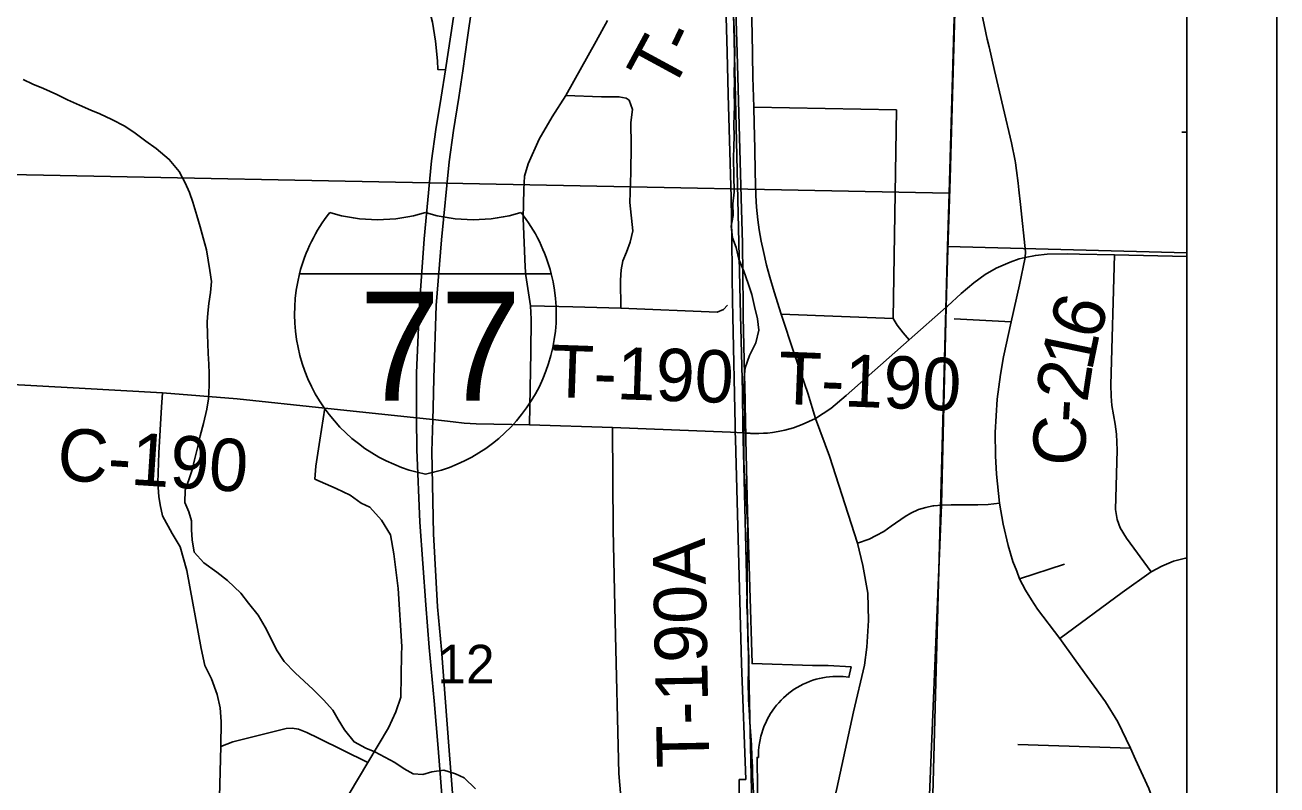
# Model space of a CAD drawing. Extents: x 0 to 34, y 0 to 22.
# Drawn here: x 8.376 to 9.735, y 19.213 to 20.038 of the extents above; entities that cross this region are included whole.
import ezdxf

# ---------------------------------------------------------------- set-up
doc = ezdxf.new("R2010")
doc.units = 0
for name, color, linetype in [('GM_X_City_Street', 7, 'Continuous'), ('GM_X_Corporation', 7, 'Continuous'), ('GM_X_County_Road', 7, 'Continuous'), ('GM_X_County_Road_Text', 7, 'Continuous'), ('GM_X_Interchange_Ramps', 7, 'Continuous'), ('GM_X_Interstate_Location', 7, 'Continuous'), ('GM_X_Interstate_Route', 7, 'Continuous'), ('GM_X_Interstate_Shield', 7, 'Continuous'), ('GM_X_Minor_River', 7, 'Continuous'), ('GM_X_Rail_Line', 7, 'Continuous'), ('GM_X_Section_Text', 7, 'Continuous'), ('GM_X_Township_Road', 7, 'Continuous'), ('GM_X_Township_Road_Text', 7, 'Continuous'), ('SH_Data', 7, 'Continuous')]:
    doc.layers.add(name, color=color, linetype=linetype)

msp = doc.modelspace()

# ---------------------------------------------------------------- linework, layer by layer
at = {"layer": 'GM_X_City_Street'}
for p, q in [((9.6316, 19.9223), (9.637, 19.9223)), ((9.4555, 19.4373), (9.5042, 19.453)), ((9.4535, 19.2572), (9.5759, 19.2532))]:
    msp.add_line(p, q, dxfattribs=at)
msp.add_lwpolyline([(9.5985, 19.4448), (9.5714, 19.4812), (9.5648, 19.4925), (9.5613, 19.5017), (9.5597, 19.5123), (9.56, 19.5251), (9.5614, 19.577), (9.5608, 19.5942), (9.5592, 19.6051), (9.5556, 19.6255), (9.5548, 19.6355), (9.5547, 19.6478), (9.5586, 19.7888)], dxfattribs=at)
at = {"layer": 'GM_X_Corporation'}
for points in [[(7.1023, 20.9204), (2.837, 20.9204), (2.837, 14.1204), (9.637, 14.1204), (9.637, 20.9204), (9.4036, 20.9204), (9.4022, 20.8667), (9.2273, 20.8723), (9.1354, 20.8749), (9.124, 20.8753), (8.9858, 20.878), (8.9676, 20.8785), (8.8663, 20.881), (8.6259, 20.8892), (8.5535, 20.8914), (8.5421, 20.8915), (8.4667, 20.8934), (8.0602, 20.9055), (7.9522, 20.9084), (7.1104, 20.9188)], [(9.637, 19.791), (9.637, 20.8648), (9.4079, 20.8705), (9.3789, 19.8558), (9.3773, 19.7981)], [(8.3589, 19.8763), (9.3789, 19.8558), (9.3773, 19.7981), (9.3514, 18.838), (8.3333, 18.8624)], [(9.637, 18.7908), (9.637, 19.791), (9.3773, 19.7981), (9.3514, 18.838), (9.3511, 18.8009)]]:
    msp.add_lwpolyline(points, close=True, dxfattribs=at)
for points in [[(9.637, 14.7553), (9.637, 20.8621)], [(9.3877, 20.1427), (9.3802, 19.8717), (9.377, 19.7721), (9.3757, 19.7325), (9.3706, 19.5177), (9.3568, 19.1851), (9.3573, 19.1731), (9.3575, 19.1703), (9.3577, 19.163), (9.3575, 19.1426), (9.3568, 19.1161), (9.3505, 18.9331), (9.349, 18.88), (9.3486, 18.8618), (9.3482, 18.8485), (9.3472, 18.8129), (9.347, 18.8053), (9.3432, 18.6624), (9.3419, 18.6564), (9.3421, 18.534), (9.3421, 18.502), (9.3401, 18.421), (9.3264, 18.0621)], [(9.3264, 18.0621), (9.3401, 18.421), (9.3421, 18.502), (9.3421, 18.534), (9.3419, 18.6564), (9.3432, 18.6624), (9.347, 18.8053), (9.3472, 18.8129), (9.3482, 18.8485), (9.3486, 18.8618), (9.349, 18.88), (9.3505, 18.9331), (9.3568, 19.1161), (9.3575, 19.1426), (9.3577, 19.163), (9.3575, 19.1703), (9.3573, 19.1731), (9.3568, 19.1851), (9.3706, 19.5177), (9.3757, 19.7325), (9.377, 19.7721), (9.3802, 19.8717), (9.3877, 20.1427)], [(9.1348, 20.1234), (9.138, 20.0088), (9.1392, 19.9629), (9.1422, 19.8512), (9.1429, 19.8057), (9.1439, 19.7345), (9.1439, 19.7335), (9.144, 19.7278), (9.1441, 19.7221), (9.1466, 19.604), (9.1468, 19.5972), (9.147, 19.5887), (9.1536, 19.3454), (9.1582, 19.2195), (9.1547, 19.2194), (9.1511, 19.2193), (9.1514, 19.1601)], [(9.1722, 19.0732), (9.1704, 19.2433), (9.1719, 19.2434), (9.1719, 19.2471), (9.1721, 19.2509), (9.1724, 19.2546), (9.173, 19.2588), (9.1737, 19.2625), (9.1746, 19.2662), (9.1756, 19.2698), (9.1767, 19.2734), (9.1783, 19.2775), (9.1798, 19.2809), (9.1814, 19.2843), (9.1832, 19.2876), (9.1851, 19.2909), (9.1893, 19.297), (9.1916, 19.2999), (9.194, 19.3027), (9.1965, 19.3055), (9.1992, 19.3081), (9.2019, 19.3106), (9.2048, 19.3129), (9.2078, 19.3152), (9.2109, 19.3173), (9.214, 19.3193), (9.2173, 19.3211), (9.2206, 19.3228), (9.224, 19.3243), (9.2274, 19.3257), (9.2309, 19.327), (9.2345, 19.3281), (9.2381, 19.329), (9.2417, 19.3298), (9.2454, 19.3304), (9.2491, 19.3309), (9.2528, 19.3311), (9.2565, 19.3313), (9.2603, 19.3312), (9.264, 19.3311), (9.2702, 19.3304), (9.2725, 19.3416), (9.2477, 19.343), (9.2307, 19.343), (9.165, 19.3451), (9.1602, 19.5104), (9.1584, 19.5883), (9.1582, 19.5968), (9.158, 19.6036), (9.1574, 19.6314), (9.1568, 19.6592), (9.1554, 19.7218), (9.1553, 19.7275), (9.1553, 19.7332), (9.1546, 19.8014), (9.1531, 19.8508), (9.1487, 20.0085), (9.1468, 20.0776)]]:
    msp.add_lwpolyline(points, dxfattribs=at)
at = {"layer": 'GM_X_County_Road'}
for points in [[(9.4223, 20.0149), (9.4203, 20.0231), (9.409, 20.0769), (9.4068, 20.0838), (9.4033, 20.0959), (9.3994, 20.1083), (9.3948, 20.1222)], [(9.1967, 19.7245), (9.1891, 19.7487), (9.1844, 19.7646), (9.1808, 19.7777), (9.1773, 19.7925), (9.175, 19.8039), (9.1728, 19.816), (9.1711, 19.8269), (9.1698, 19.8406), (9.1691, 19.8535), (9.1685, 19.8788), (9.1679, 19.9044), (9.1672, 19.9317), (9.1669, 19.9494), (9.166, 19.9817), (9.1651, 20.03), (9.1638, 20.0783)], [(9.4507, 19.8909), (9.4468, 19.9107), (9.4377, 19.949), (9.4284, 19.9892), (9.4223, 20.0149)], [(9.4547, 19.8596), (9.4538, 19.8666), (9.4521, 19.8806), (9.4511, 19.8889), (9.4507, 19.8909)], [(9.4617, 19.7862), (9.4618, 19.7921), (9.4566, 19.8435), (9.4547, 19.8596)], [(9.3772, 19.7332), (9.3922, 19.7469), (9.4057, 19.7585), (9.4181, 19.7676), (9.43, 19.7745), (9.4451, 19.7811), (9.4552, 19.7846), (9.4617, 19.7862)], [(9.4524, 19.4454), (9.4483, 19.4561), (9.4431, 19.4732), (9.4377, 19.4966), (9.4337, 19.5194), (9.4305, 19.5509), (9.4293, 19.5707), (9.4289, 19.5962), (9.4312, 19.6323), (9.4349, 19.659), (9.4381, 19.6781), (9.4465, 19.7161), (9.4554, 19.7563), (9.4617, 19.7862)], [(9.4617, 19.7862), (9.4727, 19.7884), (9.4853, 19.7897), (9.5079, 19.7901), (9.5206, 19.7898)], [(9.5206, 19.7898), (9.5586, 19.7888), (9.637, 19.7873)], [(9.1625, 19.5952), (9.1635, 19.5951), (9.1684, 19.595), (9.1725, 19.595), (9.1773, 19.5952), (9.1817, 19.5955), (9.1872, 19.5962), (9.1932, 19.5971), (9.2006, 19.5986), (9.2099, 19.6012), (9.2193, 19.6046), (9.234, 19.6114), (9.2506, 19.6222), (9.2672, 19.6362), (9.3357, 19.6968), (9.3759, 19.732), (9.3772, 19.7332)], [(9.243, 19.1481), (9.257, 19.2097), (9.2753, 19.2929), (9.2871, 19.3435), (9.2896, 19.3629), (9.2914, 19.3921), (9.2908, 19.4217), (9.2852, 19.4516), (9.2795, 19.4758), (9.2491, 19.5703), (9.234, 19.6114), (9.2257, 19.6387), (9.2108, 19.6817), (9.1967, 19.7245)], [(8.3488, 19.6489), (8.4344, 19.6443), (8.5247, 19.6393), (8.606, 19.6325), (8.701, 19.6225)], [(8.701, 19.6225), (8.8006, 19.612), (8.8183, 19.61), (8.8403, 19.6078), (8.8524, 19.6062), (8.8656, 19.6054), (8.9233, 19.6043), (9.0134, 19.6015), (9.1415, 19.5963)], [(9.1415, 19.5963), (9.1554, 19.5957), (9.1595, 19.5954), (9.1625, 19.5952)], [(9.2795, 19.4758), (9.2921, 19.4803), (9.2996, 19.4841), (9.308, 19.4887), (9.3161, 19.4942), (9.3314, 19.5049), (9.3375, 19.5086), (9.3456, 19.5124), (9.3536, 19.5147), (9.3614, 19.5163)], [(9.3614, 19.5163), (9.3624, 19.5165), (9.3708, 19.5172), (9.3812, 19.5174), (9.4102, 19.5175), (9.4214, 19.518), (9.4337, 19.5194)], [(9.4993, 19.3725), (9.5668, 19.4222), (9.5985, 19.4448), (9.6098, 19.4511), (9.6227, 19.4564), (9.6356, 19.4596), (9.637, 19.4598)], [(9.608, 19.176), (9.5958, 19.2096), (9.5815, 19.241), (9.5759, 19.2532), (9.5621, 19.2818), (9.5489, 19.3036), (9.5165, 19.3481), (9.4993, 19.3725), (9.4749, 19.4043), (9.4684, 19.4143), (9.462, 19.4248), (9.4555, 19.4373), (9.4524, 19.4454)]]:
    msp.add_lwpolyline(points, dxfattribs=at)
at = {"layer": 'GM_X_Interchange_Ramps'}
msp.add_lwpolyline([(8.6899, 20.3386), (8.6874, 20.3341), (8.6787, 20.3193), (8.6745, 20.3085), (8.6725, 20.3013), (8.6712, 20.2917), (8.6704, 20.283), (8.6712, 20.273), (8.6726, 20.2598), (8.6767, 20.2451), (8.6831, 20.2301), (8.7001, 20.2081), (8.7688, 20.1341), (8.7796, 20.1219), (8.7885, 20.1099), (8.7962, 20.0973), (8.805, 20.0811), (8.8125, 20.0622), (8.818, 20.0414), (8.8214, 20.0209), (8.8233, 19.9995), (8.8239, 19.9901), (8.832, 19.9897)], dxfattribs=at)
at = {"layer": 'GM_X_Interstate_Route'}
for points in [[(8.8273, 19.9603), (8.832, 19.9897), (8.8381, 20.0277), (8.8472, 20.0907), (8.8602, 20.1746), (8.8736, 20.2591), (8.8763, 20.2792), (8.8862, 20.3413), (8.8962, 20.4047), (8.9061, 20.4741), (8.9155, 20.533), (8.9181, 20.5506), (8.926, 20.5995), (8.9382, 20.6828), (8.9516, 20.774), (8.9678, 20.878)], [(8.8465, 19.9599), (8.8511, 19.9887), (8.8561, 20.0249), (8.8651, 20.0879), (8.8781, 20.1718), (8.8916, 20.2563), (8.8946, 20.2767), (8.9044, 20.3409), (8.9144, 20.4042), (8.9243, 20.4736), (8.9337, 20.5325), (8.937, 20.5487), (8.9564, 20.6824), (8.9699, 20.7735), (8.986, 20.8775)], [(8.8006, 19.6249), (8.8006, 19.6607), (8.8039, 19.7349), (8.8088, 19.8063), (8.817, 19.891), (8.8216, 19.925), (8.8273, 19.9603)], [(8.8186, 19.623), (8.8195, 19.6549), (8.822, 19.7339), (8.8279, 19.8053), (8.8361, 19.89), (8.8408, 19.9241), (8.8465, 19.9599)], [(8.8989, 18.3509), (8.895, 18.3799), (8.8917, 18.412), (8.8886, 18.4533), (8.8825, 18.5322), (8.8739, 18.6411), (8.8688, 18.703), (8.859, 18.8212), (8.8549, 18.8749), (8.8414, 19.0423), (8.8359, 19.1114), (8.8301, 19.1795), (8.8286, 19.198), (8.824, 19.2534), (8.8197, 19.3047), (8.8144, 19.3626), (8.8108, 19.4089), (8.8041, 19.4986), (8.8011, 19.5776), (8.8006, 19.612), (8.8006, 19.6249)], [(8.8406, 19.1954), (8.8361, 19.2508), (8.8278, 19.3603), (8.8236, 19.4067), (8.819, 19.486), (8.8172, 19.5753), (8.8183, 19.61), (8.8186, 19.623)]]:
    msp.add_lwpolyline(points, dxfattribs=at)
at = {"layer": 'GM_X_Interstate_Shield'}
for p, q in [((8.6736, 19.7683), (8.9469, 19.7683)), ((8.9469, 19.7683), (8.6736, 19.7683)), ((8.9469, 19.7683), (8.6736, 19.7683))]:
    msp.add_line(p, q, dxfattribs=at)
for centre, start, end in [((8.8458, 19.7248), 141.669, 165.8066), ((8.7584, 20.0047), 253.0091, 286.9909), ((8.8622, 20.0047), 253.0091, 286.9909), ((8.7748, 19.7248), 14.1934, 38.331), ((8.8458, 19.7248), 165.8066, 258.463), ((8.7748, 19.7248), 281.537, 14.1934)]:
    msp.add_arc(centre, 0.1776, start, end, dxfattribs=at)
at = {"layer": 'GM_X_Minor_River'}
for points in [[(9.145, 20.046), (9.1455, 20.035), (9.1461, 20.0205), (9.1462, 20.0099), (9.1459, 19.9985), (9.1457, 19.9867), (9.1458, 19.9761), (9.1456, 19.9659), (9.1458, 19.9507), (9.1455, 19.9404), (9.1453, 19.9305), (9.1454, 19.9176), (9.1452, 19.9066), (9.1449, 19.8937), (9.1454, 19.8569), (9.144, 19.8443), (9.1446, 19.8318), (9.1424, 19.82), (9.1437, 19.8075), (9.1476, 19.7969), (9.1508, 19.7844), (9.1559, 19.7712), (9.1606, 19.758), (9.1646, 19.7459), (9.1677, 19.733), (9.1709, 19.7194), (9.1722, 19.7072), (9.169, 19.6935), (9.1623, 19.6798), (9.1576, 19.6661), (9.1565, 19.6558), (9.1559, 19.6425), (9.1565, 19.6296)], [(8.3734, 19.9793), (8.3841, 19.9744), (8.3955, 19.9696), (8.41, 19.963), (8.4218, 19.9574), (8.4348, 19.9515), (8.447, 19.9459), (8.4569, 19.9419), (8.4699, 19.936), (8.484, 19.9285), (8.4951, 19.9211), (8.5066, 19.9125), (8.518, 19.9043)], [(8.518, 19.9043), (8.5322, 19.8926), (8.543, 19.8795), (8.5496, 19.867), (8.5543, 19.8565), (8.5578, 19.8462), (8.5621, 19.8315), (8.5657, 19.8194), (8.5689, 19.8073), (8.5725, 19.7944), (8.5745, 19.783), (8.5761, 19.772), (8.5782, 19.7599), (8.5768, 19.7481), (8.5751, 19.736), (8.574, 19.7257), (8.5734, 19.7162), (8.5736, 19.7022), (8.5741, 19.6927), (8.5746, 19.682), (8.5751, 19.6703), (8.5756, 19.66), (8.5754, 19.6471), (8.5748, 19.6327), (8.573, 19.6213), (8.5694, 19.6057), (8.5658, 19.5923), (8.5633, 19.5809), (8.5597, 19.5665), (8.5571, 19.5554), (8.5538, 19.5459), (8.5495, 19.5333), (8.5492, 19.52), (8.5535, 19.5098), (8.5563, 19.5), (8.5564, 19.4905), (8.5569, 19.4795), (8.5594, 19.4662), (8.5697, 19.4546), (8.5839, 19.4445), (8.5954, 19.4355), (8.61, 19.4216), (8.6184, 19.4107), (8.6288, 19.3979), (8.6362, 19.3847), (8.6428, 19.3719), (8.6486, 19.3602), (8.6571, 19.3474), (8.669, 19.335), (8.6786, 19.326), (8.6886, 19.317), (8.6997, 19.3057), (8.7097, 19.2945), (8.7155, 19.2843), (8.7225, 19.2734), (8.7329, 19.2602), (8.7458, 19.2535), (8.7554, 19.2494), (8.7664, 19.2435), (8.7771, 19.2379), (8.7874, 19.2308), (8.797, 19.2256), (8.8076, 19.2246), (8.8174, 19.2278), (8.8303, 19.2294), (8.8429, 19.2254), (8.8524, 19.221), (8.8647, 19.2093)], [(9.1565, 19.6296), (9.157, 19.6171), (9.1564, 19.6049), (9.1562, 19.5894), (9.1559, 19.5791), (9.1561, 19.5673), (9.1566, 19.554), (9.1571, 19.5427), (9.158, 19.5317), (9.1589, 19.5214), (9.1594, 19.51), (9.1604, 19.4937), (9.1601, 19.4827), (9.1603, 19.4717), (9.16, 19.4611), (9.1598, 19.4485), (9.1596, 19.4326), (9.1597, 19.4227), (9.1595, 19.4083), (9.1601, 19.395), (9.1604, 19.3711), (9.1613, 19.3597), (9.1614, 19.3502), (9.1611, 19.3373), (9.1609, 19.3259), (9.1611, 19.3062), (9.1617, 19.2952), (9.1626, 19.2811), (9.1644, 19.2569), (9.1649, 19.2447), (9.1654, 19.2326), (9.1656, 19.2231), (9.1661, 19.2136), (9.1666, 19.2026)]]:
    msp.add_lwpolyline(points, dxfattribs=at)
at = {"layer": 'GM_X_Rail_Line'}
msp.add_lwpolyline([(9.1945, 18.3539), (9.1905, 18.3737), (9.1876, 18.3897), (9.1856, 18.4063), (9.1839, 18.4181), (9.1825, 18.435), (9.1817, 18.4513), (9.1794, 18.5286), (9.1776, 18.6187), (9.177, 18.6584), (9.1761, 18.6872), (9.1751, 18.7317), (9.1725, 18.8369), (9.1713, 18.9007), (9.1704, 18.9377), (9.169, 19.0032), (9.1673, 19.0755), (9.1653, 19.1591), (9.1608, 19.3675), (9.155, 19.6038), (9.1547, 19.6403), (9.1525, 19.7238), (9.1393, 20.2883)], dxfattribs=at)
at = {"layer": 'GM_X_Township_Road'}
for p, q in [((9.1669, 19.9494), (9.322, 19.9464)), ((9.1967, 19.7245), (9.3181, 19.7197)), ((9.3844, 19.7194), (9.4465, 19.7161))]:
    msp.add_line(p, q, dxfattribs=at)
for points in [[(8.9243, 19.7335), (8.9195, 19.7666), (8.9185, 19.7754), (8.9163, 19.8289), (8.9172, 19.86), (8.9179, 19.8744), (8.9219, 19.8876), (8.9337, 19.9147), (8.9478, 19.9388), (8.9627, 19.9619), (8.9957, 20.021), (9.008, 20.0435)], [(8.9627, 19.9619), (9.0015, 19.9606), (9.0204, 19.9606), (9.0283, 19.9589), (9.0317, 19.957)], [(9.0224, 19.731), (9.0223, 19.7615), (9.0229, 19.7725), (9.0246, 19.7825), (9.0285, 19.7917), (9.0326, 19.8026), (9.0356, 19.8149), (9.0324, 19.8458), (9.0333, 19.8784), (9.0338, 19.9076), (9.0335, 19.9326), (9.0353, 19.9467), (9.0317, 19.957)], [(9.3357, 19.6968), (9.3289, 19.7044), (9.3225, 19.7126), (9.3181, 19.7197), (9.322, 19.9464)], [(8.9233, 19.6043), (8.9249, 19.6832), (8.9251, 19.7192), (8.9243, 19.7335), (8.9705, 19.7325), (9.0224, 19.731), (9.1272, 19.7268), (9.1339, 19.7297), (9.1383, 19.7343)], [(8.6276, 19.0124), (8.6214, 19.0333), (8.6138, 19.0459), (8.5937, 19.0718), (8.5867, 19.0863), (8.5842, 19.1045), (8.5883, 19.2551), (8.5886, 19.2822), (8.5874, 19.2971), (8.5841, 19.3116), (8.5781, 19.3287), (8.5709, 19.3432), (8.567, 19.3616), (8.5512, 19.4464), (8.544, 19.4721), (8.5354, 19.4865), (8.5249, 19.5056), (8.5222, 19.5174), (8.5209, 19.5266), (8.5199, 19.5414), (8.5207, 19.5741), (8.5236, 19.6237), (8.5247, 19.6393)], [(8.7844, 19.3549), (8.7846, 19.3639), (8.7806, 19.4268), (8.7759, 19.4645), (8.7725, 19.485), (8.7626, 19.5008), (8.75, 19.515), (8.7406, 19.5194), (8.7287, 19.528), (8.7133, 19.5351), (8.6904, 19.5454), (8.6914, 19.5594), (8.6957, 19.5878), (8.701, 19.6225)], [(9.0225, 19.1458), (9.0225, 19.1497), (9.0224, 19.2004), (9.0202, 19.2259), (9.0163, 19.391), (9.0143, 19.4905), (9.0134, 19.6015)], [(8.7051, 19.0206), (8.6985, 19.0756), (8.6982, 19.0878), (8.6982, 19.103), (8.6988, 19.1152), (8.7017, 19.1263), (8.7055, 19.1395), (8.7187, 19.1833), (8.7225, 19.1924), (8.7275, 19.2037), (8.7477, 19.2377), (8.7703, 19.2755), (8.7782, 19.2929), (8.7836, 19.3089), (8.7844, 19.3549)], [(8.5883, 19.2551), (8.6012, 19.2601), (8.6592, 19.2746), (8.6658, 19.2749), (8.6724, 19.274), (8.6815, 19.2702), (8.6941, 19.2642), (8.7477, 19.2377)]]:
    msp.add_lwpolyline(points, dxfattribs=at)
at = {"layer": 'SH_Data'}
msp.add_line((9.7349, 21.0001), (9.7349, 14.0001), dxfattribs=at)

# ---------------------------------------------------------------- texts
at = {"layer": 'GM_X_County_Road_Text'}
for s, height, rotation, p in [('6', 0.0568, 72.9015, (9.5407, 19.6944)), ('1', 0.0568, 78.3145, (9.534, 19.6615)), ('2', 0.0568, 81.3496, (9.5289, 19.6277)), ('-', 0.0568, 86.5712, (9.5276, 19.6057)), ('C', 0.0568, 89.1413, (9.5269, 19.5597)), ('C-190', 0.05682, 356.2592, (8.4094, 19.5447))]:
    msp.add_text(s, height=height, rotation=rotation, dxfattribs=at).set_placement(p)
at = {"layer": 'GM_X_Interstate_Location'}
for s in ['-', '.', ',']:
    msp.add_text(s, height=0.000189, dxfattribs=at).set_placement((8.8103, 19.6928))
msp.add_text('77', height=0.000189, rotation=0, dxfattribs=at).set_placement((8.7716, 19.6536))
at = {"layer": 'GM_X_Interstate_Shield'}
msp.add_text('77', height=0.11837, dxfattribs=at).set_placement((8.7384, 19.6307))
at = {"layer": 'GM_X_Section_Text'}
msp.add_text('12', height=0.04186, rotation=0, dxfattribs=at).set_placement((8.8232, 19.3237))
at = {"layer": 'GM_X_Township_Road_Text'}
for s, height, rotation, p in [('T', 0.0568, 61.5257, (9.0772, 19.964)), ('-', 0.0568, 64.5841, (9.0989, 20.0043)), ('T-190', 0.05682, 358.054, (8.9457, 19.6347)), ('T-190', 0.05682, 357.7544, (9.1927, 19.6273)), ('T-190A', 0.05682, 91.0853, (9.1186, 19.2327))]:
    msp.add_text(s, height=height, rotation=rotation, dxfattribs=at).set_placement(p)

doc.saveas('drawing.dxf')
